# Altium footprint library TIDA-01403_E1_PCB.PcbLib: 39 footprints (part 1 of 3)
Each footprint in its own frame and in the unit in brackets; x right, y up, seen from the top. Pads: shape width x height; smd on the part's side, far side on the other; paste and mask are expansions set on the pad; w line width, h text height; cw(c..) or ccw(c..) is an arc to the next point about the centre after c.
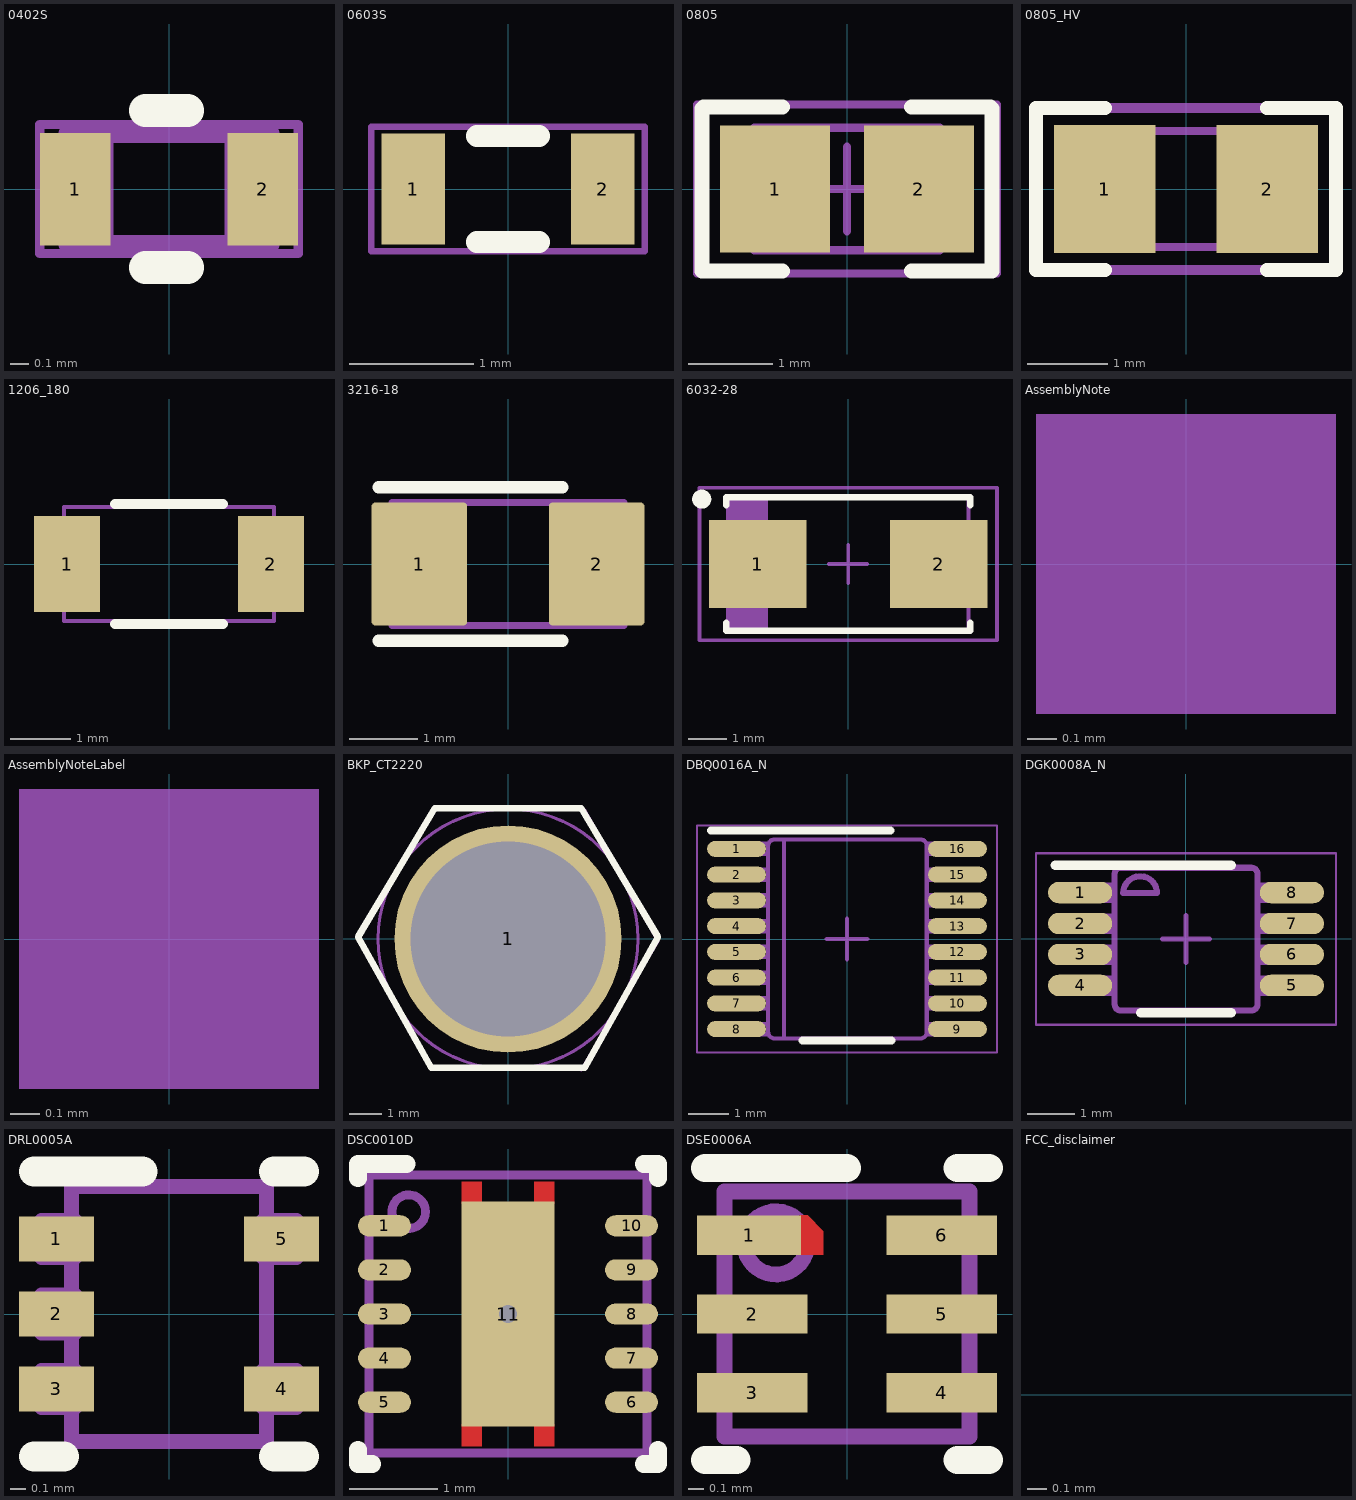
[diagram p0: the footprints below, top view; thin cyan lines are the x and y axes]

## 0402S [mil] "Based on C0402S footprint from PADS legacy"
height 23.62
pads (2):
  rect 15x24 smd: 1(-20,0) 2(20,0)
Top Overlay:
  lines w7: -5,-16.73 4,-16.73 ; -5,16.73 4,16.73
Mechanical 5:
  lines w1.97: -27.56,-13.78 27.56,-13.78 27.56,13.78 -27.56,13.78 -27.56,-13.78
  text ".Designator" at -21.65,-5.91 h25
Mechanical 13:
  lines w3.94: -13.78,-11.81 -13.78,11.81 ; 13.78,-11.81 13.78,11.81 ; -21.65,-11.81 -21.65,11.81 21.65,11.81 21.65,-11.81 -21.65,-11.81
3D body: height 23.62, standoff 0, extent -21.63,-11.79 -13.8,11.79
3D body: height 23.62, standoff 0, extent -13.76,-11.79 13.76,11.79
3D body: height 23.62, standoff 0, extent 13.8,-11.79 21.63,11.79

## 0603S [mil]
height 39.37
pads (2):
  rect 20x35 smd: 1(-30,0) 2(30,0)
Top Overlay:
  lines w7: -9.84,-16.73 9.84,-16.73 ; -9.84,16.73 9.84,16.73
Mechanical 5:
  lines w1.97: -43.31,-19.68 43.31,-19.68 43.31,19.68 -43.31,19.68 -43.31,-19.68
  text ".Designator" at -32.48,-8.86 h30
3D body: height 39.37, standoff 0, extent -34.43,-18.68 -21.67,18.68
3D body: height 39.37, standoff 0, extent -21.63,-18.68 21.63,18.68
3D body: height 39.37, standoff 0, extent 21.67,-18.68 34.43,18.68

## 0805 [mm] "0805 from SM-752 data"
height 1.45
pads (2):
  rect 1.3x1.5 smd: 1(-0.85,0) 2(0.85,0)
Top Overlay:
  lines w0.178: -0.762,-0.968 -1.717,-0.968 -1.717,0.95 -1.699,0.968 -0.762,0.968 ; 0.762,-0.968 1.717,-0.968 1.717,0.95 1.699,0.968 0.762,0.968
Mechanical 5:
  lines w0.1: -1.775,-1 -1.775,1 1.775,1 1.775,-1 -1.775,-1
  text ".Designator" at -1.525,-0.425 h0.76
Mechanical 13:
  lines w0.1: -0.65,-0.725 -0.65,0.725 ; 0.65,-0.725 0.65,0.725 ; -1.1,-0.725 -1.1,0.725 1.1,0.725 1.1,-0.725 -1.1,-0.725
Mechanical 15:
  lines w0.1: -0.5,0 0.5,0 ; 0,-0.5 0,0.5 ; -1.775,-1 -1.775,1 1.775,1 1.775,-1 -1.775,-1
3D body: height 1.45, standoff 0, extent 0.651,-0.724 1.099,0.724
3D body: height 1.45, standoff 0, extent -0.649,-0.724 0.649,0.724
3D body: height 1.45, standoff 0, extent -1.099,-0.724 -0.651,0.724

## 0805_HV [mil] "0805 with 30mil clearance between pads"
height 57.09
pads (2):
  rect 50x63 smd: 1(-40,0) 2(40,0)
Top Overlay:
  lines w7: -40,-40 -74,-40 -74,0 -74,40 -40,40 ; 40,-40 74,-40 74,0 74,40 40,40
Mechanical 5:
  lines w5: -74,-40 74,-40 74,40 -74,40 -74,-40
  text ".Designator" at -64,-17 h30
Mechanical 13:
  lines w3.94: -25.59,-28.54 -25.59,28.54 ; 25.59,-28.54 25.59,28.54 ; -43.31,-28.54 43.31,-28.54 43.31,28.54 -43.31,28.54 -43.31,-28.54
3D body: height 57.09, standoff 0, extent -43.29,-28.52 -25.61,28.52
3D body: height 57.09, standoff 0, extent -25.57,-28.52 25.57,28.52
3D body: height 57.09, standoff 0, extent 25.61,-28.52 43.29,28.52

## 1206_180 [mm] "1206_180"
height 1.8
pads (2):
  rect 1.1x1.6 smd: 1(-1.7,0) 2(1.7,0)
Top Overlay:
  lines w0.17: -0.9,-1 0.9,-1 ; -0.9,1 0.9,1
Mechanical 5:
  lines w0.07: -1.75,-0.95 1.75,-0.95 1.75,0.95 -1.75,0.95 -1.75,-0.95
  text ".Designator" at -1.5,-0.4 h0.76
3D body: height 1.8, standoff 0, extent -1.749,-0.949 -1.301,0.949
3D body: height 1.8, standoff 0, extent -1.299,-0.949 1.299,0.949
3D body: height 1.8, standoff 0, extent 1.301,-0.949 1.749,0.949

## 3216-18 [mm] "Based on AVX recommendation in http://www.avx.com/download/software/literature/AVX-Footprint-Library.pdf"
height 1.8
pads (2):
  rrect7% 1.4x1.8 smd: 1(-1.3,0) 2(1.3,0)
Top Overlay:
  lines w0.178: -1.9,-1.125 0.8,-1.125 ; -1.9,1.125 0.8,1.125
Mechanical 5:
  rectangle: -1.7,-0.9 -1.175,0.9
  lines w0.1: -1.175,-0.9 -1.175,0.9 ; -1.7,-0.9 -1.7,0.9 1.7,0.9 1.7,-0.9 -1.7,-0.9
  text ".Designator" at -0.95,-0.325 h0.76
3D body "3216-18.stp": height 1.82, standoff 0.01, extent -1.7,-0.9 1.7,0.9

## 6032-28 [mm] "Medium Density IPC based on Vishay Sprague 293D datasheet."
height 2.8
pads (2):
  rect 2.55x2.3 smd: 1(-2.375,0) 2(2.375,0)
Top Overlay:
  circle w0.25: c-3.839,1.7 r0.125
  lines w0.178: -3.2,-1.539 -3.2,-1.75 3.2,-1.75 3.2,-1.539 ; -3.2,1.539 -3.2,1.75 3.2,1.75 3.2,1.539
Mechanical 5:
  rectangle: -3.15,-1.75 -2.15,1.75
  lines w0.1: -2.15,-1.75 -2.15,1.75 ; -3.15,-1.75 -3.15,1.75 3.15,1.75 3.15,-1.75 -3.15,-1.75
  text ".Designator" at -1.85,-0.525 h0.76
Mechanical 15:
  lines w0.1: -0.5,0 0.5,0 ; 0,-0.5 0,0.5 ; -3.9,-2 3.9,-2 3.9,2 -3.9,2 -3.9,-2
3D body: height 2.8, standoff 0, extent -3.15,-1.75 3.15,1.75
3D body: height 2.8, standoff 2.8, extent -3.149,-1.749 -2.151,1.749

## AssemblyNote [mm] "Assembly Note"
Mechanical 5:
  rectangle: -0.508,-0.508 0.508,0.508
  text ".Designator" at -4.191,-0.508 h0.76
  text ".Comment" at 1.143,-0.508 h0.76

## AssemblyNoteLabel [mm] "Assembly Note for PCB Labels"
Mechanical 5:
  rectangle: -0.508,-0.508 0.508,0.508
  text ".Designator" at -4.191,-0.508 h0.76
  text "Install label in silkscreened box after final wash.  Text shall be 8 pt font.  Text shall be per the Label Table in the PDF schematic." at 1.143,-0.508 h0.76

## BKP_CT2220 [mm] "Banana Jack Connector Standard Banana Threaded, External (Nut), TH"
height 4.54
pads (1):
  round 7 hole 6: 1(0,0)
Top Overlay:
  lines w0.2: -4.618,0.061 -2.256,4.03 2.256,4.03 4.618,0.061 2.362,-3.969 -2.362,-3.969 -4.618,0.061
Mechanical 5:
  circle w0.1: c0,0 r3
  circle w0.1: c0,0 r4
  lines w0.1: -4.618,0.061 -2.362,-3.969 2.256,-4.03 4.618,-0.061 2.362,3.969 -2.256,4.03 -4.618,0.061
  text ".Designator" at -2.2,-0.6 h0.76
3D body "CT2220.stp": height 4, standoff -19, extent -4.619,-4 4.619,4

## DBQ0016A_N [mm] "SOP, 16-Leads, Body 4.9x3.9mm, Pitch 0.635mm, IPC Medium Density"
height 1.76
pads (16):
  oval 1.45x0.4 smd: 1(-2.725,2.222) 2(-2.725,1.587) 3(-2.725,0.953) 4(-2.725,0.318) 5(-2.725,-0.318) 6(-2.725,-0.953) 7(-2.725,-1.587) 8(-2.725,-2.222) 9(2.725,-2.222) 10(2.725,-1.587) 11(2.725,-0.953) 12(2.725,-0.318) 13(2.725,0.318) 14(2.725,0.953) 15(2.725,1.587) 16(2.725,2.222)
Top Overlay:
  lines w0.2: -3.35,2.675 1.075,2.675 ; -1.1,-2.5 1.1,-2.5
Mechanical 5:
  drawing of 209 lines, arcs and shapes, not listed
  text ".Designator" at -0.5,1.875 h0.76
Mechanical 15:
  lines w0.05: -3.7,-2.8 -3.7,2.8 3.7,2.8 3.7,-2.8 -3.7,-2.8
  lines w0.1: -0.5,0 0.5,0 ; 0,-0.5 0,0.5
3D body "DBQ0016A.stp": height 1.63, standoff 0, extent -3.011,-2.451 3.011,2.451

## DGK0008A_N [mm] "TSOP, 8-Leads, Body 3x3mm, Pitch 0.65mm, IPC Medium Density"
height 1.1
pads (8):
  oval 1.35x0.45 smd: 1(-2.225,0.975) 2(-2.225,0.325) 3(-2.225,-0.325) 4(-2.225,-0.975) 5(2.225,-0.975) 6(2.225,-0.325) 7(2.225,0.325) 8(2.225,0.975)
Top Overlay:
  lines w0.2: -2.75,1.55 0.95,1.55 ; -0.95,-1.55 0.95,-1.55
Mechanical 5:
  lines w0.127: -2.45,-1.131 -2.21,-1.131 -2.091,-1.131 -2.087,-1.131 -1.784,-1.131 -1.498,-1.131 -1.498,-0.826 -1.784,-0.826 -2.087,-0.826 -2.091,-0.826 -2.21,-0.826 -2.45,-0.826 -2.45,-1.131 ; -2.45,-0.48 -2.21,-0.48 -2.091,-0.48 -2.087,-0.48 -1.784,-0.48 -1.498,-0.48 -1.498,-0.175 -1.784,-0.175 -2.087,-0.175 -2.091,-0.175 -2.21,-0.175 -2.45,-0.175 -2.45,-0.48 ; -2.45,0.17 -2.21,0.17 -2.091,0.17 -2.087,0.17 -1.784,0.17 -1.498,0.17 -1.498,0.475 -1.784,0.475 -2.087,0.475 -2.091,0.475 -2.21,0.475 -2.45,0.475 -2.45,0.17 ; -2.45,0.82 -2.21,0.82 -2.091,0.82 -2.087,0.82 -1.784,0.82 -1.498,0.82 -1.498,1.125 -1.784,1.125 -2.087,1.125 -2.091,1.125 -2.21,1.125 -2.45,1.125 -2.45,0.82 ; -1.497,-1.377 ccw(c-1.37,-1.374) -1.373,-1.501 -1.371,-1.501 1.373,-1.501 1.375,-1.501 ccw(c1.373,-1.374) 1.5,-1.377 1.5,-1.374 1.5,1.369 1.5,1.372 ccw(c1.373,1.369) 1.375,1.496 1.373,1.496 -1.371,1.496 -1.373,1.496 ccw(c-1.37,1.369) -1.497,1.372 -1.498,1.369 -1.498,-1.374 -1.497,-1.377 ; -1.32,0.962 cw(c-0.964,0.962) -0.609,0.962 -1.32,0.962 ; 1.5,-1.131 1.5,-0.826 1.786,-0.826 2.089,-0.826 2.093,-0.826 2.213,-0.826 2.452,-0.826 2.452,-1.131 2.213,-1.131 2.093,-1.131 2.089,-1.131 1.786,-1.131 1.5,-1.131 ; 1.5,-0.48 1.5,-0.175 1.786,-0.175 2.089,-0.175 2.093,-0.175 2.213,-0.175 2.452,-0.175 2.452,-0.48 2.213,-0.48 2.093,-0.48 2.089,-0.48 1.786,-0.48 1.5,-0.48 ; 1.5,0.17 1.5,0.475 1.786,0.475 2.089,0.475 2.093,0.475 2.213,0.475 2.452,0.475 2.452,0.17 2.213,0.17 2.093,0.17 2.089,0.17 1.786,0.17 1.5,0.17 ; 1.5,0.82 1.5,1.125 1.786,1.125 2.089,1.125 2.093,1.125 2.213,1.125 2.452,1.125 2.452,0.82 2.213,0.82 2.093,0.82 2.089,0.82 1.786,0.82 1.5,0.82
  text ".Designator" at -1.15,-0.3 h0.76
Mechanical 15:
  lines w0.05: -3.15,-1.8 3.15,-1.8 3.15,1.8 -3.15,1.8 -3.15,-1.8
  lines w0.1: -0.5,0 0.5,0 ; 0,-0.5 0,0.5
3D body "DGK0008A.stp": height 0.96, standoff 0, extent -2.451,-1.499 2.451,1.499

## DRL0005A [mm] "SOTFL, 5-Flat Leads, Body 1.2x1.6x0.6mm, Pitch 0.5mm, TI recommended"
height 0.6
pads (5):
  rect 0.5x0.3 smd: 1(-0.75,0.5) 2(-0.75,0) 3(-0.75,-0.5) 4(0.75,-0.5) 5(0.75,0.5)
Top Overlay:
  lines w0.2: -0.9,-0.95 -0.7,-0.95 ; -0.9,0.95 -0.175,0.95 ; 0.7,-0.95 0.9,-0.95 ; 0.7,0.95 0.9,0.95
Mechanical 5:
  lines w0.1: -0.65,-0.625 -0.65,-0.85 0.65,-0.85 0.65,-0.625 ; -0.65,-0.375 -0.65,-0.125 ; -0.65,0.125 -0.65,0.375 ; -0.65,0.625 -0.65,0.85 0.65,0.85 0.65,0.625 ; 0.65,-0.375 0.65,0.375 ; -0.85,-0.625 -0.85,-0.375 -0.627,-0.375 -0.627,-0.625 -0.85,-0.625 ; -0.85,-0.125 -0.627,-0.125 -0.627,0.125 -0.85,0.125 -0.85,-0.125 ; -0.85,0.375 -0.85,0.625 -0.627,0.625 -0.627,0.375 -0.85,0.375 ; 0.627,-0.625 0.627,-0.375 0.85,-0.375 0.85,-0.625 0.627,-0.625 ; 0.627,0.375 0.627,0.625 0.85,0.625 0.85,0.375 0.627,0.375
  text ".Designator" at -0.15,0.55 h0.76
3D body "DRL0005A.stp": height 0.62, standoff 0.02, extent -0.85,-0.85 0.85,0.85

## DSC0010D [mm]
height 0.8
pads (11):
  oval 0.6x0.24 smd: 1(-1.4,1) 2(-1.4,0.5) 3(-1.4,0) 4(-1.4,-0.5) 5(-1.4,-1) 6(1.4,-1) 7(1.4,-0.5) 8(1.4,0) 9(1.4,0.5) 10(1.4,1)
  rect 1.05x2.55 smd paste-1: 11(0,0)
via 0,0 diameter 0.5 hole 0.2
Top Layer:
  rectangle: -0.525,1.25 -0.295,1.5
  region: 0.525,1.5 0.295,1.5 0.295,1.25 0.525,1.25
  region: 0.525,-1.25 0.295,-1.25 0.295,-1.5 0.525,-1.5
  rectangle: -0.525,-1.5 -0.295,-1.25
Top Overlay:
  lines w0.2: -1.7,-1.54 -1.7,-1.7 -1.54,-1.7 ; -1.7,1.54 -1.7,1.7 -1.15,1.7 ; 1.54,-1.7 1.7,-1.7 1.7,-1.54 ; 1.54,1.7 1.7,1.7 1.7,1.54
Top Paste:
  region: -0.498,-0.1 -0.498,-1.225 0.498,-1.225 0.498,-0.1
  region: 0.498,0.1 0.498,1.225 -0.498,1.225 -0.498,0.1
Mechanical 5:
  circle w0.1: c-1.125,1.16 r0.19
  lines w0.1: 1.575,-1.575 1.575,1.575 -1.575,1.575 -1.575,-1.575 1.55,-1.575 1.575,-1.55
  text ".Designator" at -1.4,-0.325 h0.76
3D body: height 0.8, standoff 0, extent -1.576,-1.576 1.576,1.576
3D body: height 0.81, standoff 0.7, extent -1.315,0.97 -0.935,1.349

## DSE0006A [mm] "TI recommended land pattern"
height 0.8
pads (6):
  rect 0.66x0.25 smd: 1(-0.62,0.5)
  rect 0.7x0.25 smd: 2(-0.6,0) 3(-0.6,-0.5) 4(0.6,-0.5) 5(0.6,0) 6(0.6,0.5)
Top Layer:
  region: -0.3,0.625 -0.25,0.625 -0.15,0.525 -0.15,0.375 -0.3,0.375
Top Overlay:
  lines w0.178: -0.9,-0.925 -0.7,-0.925 ; -0.9,0.925 0,0.925 ; 0.7,-0.925 0.9,-0.925 ; 0.7,0.925 0.9,0.925
Mechanical 5:
  circle w0.1: c-0.45,0.45 r0.2
  lines w0.1: -0.775,-0.775 -0.775,0.775 0.775,0.775 0.775,-0.775 -0.775,-0.775
  text ".Designator" at -0.575,-0.325 h0.76
3D body: height 0.8, standoff 0, extent -0.774,-0.774 0.774,0.774
3D body: height 0.8, standoff 0.76, extent -0.548,0.362 -0.352,0.558

## FCC_disclaimer [mm]
Top Overlay:
  text "For evaluation only; not FCC approved for resale." at -15.928,-0.353 h1.52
